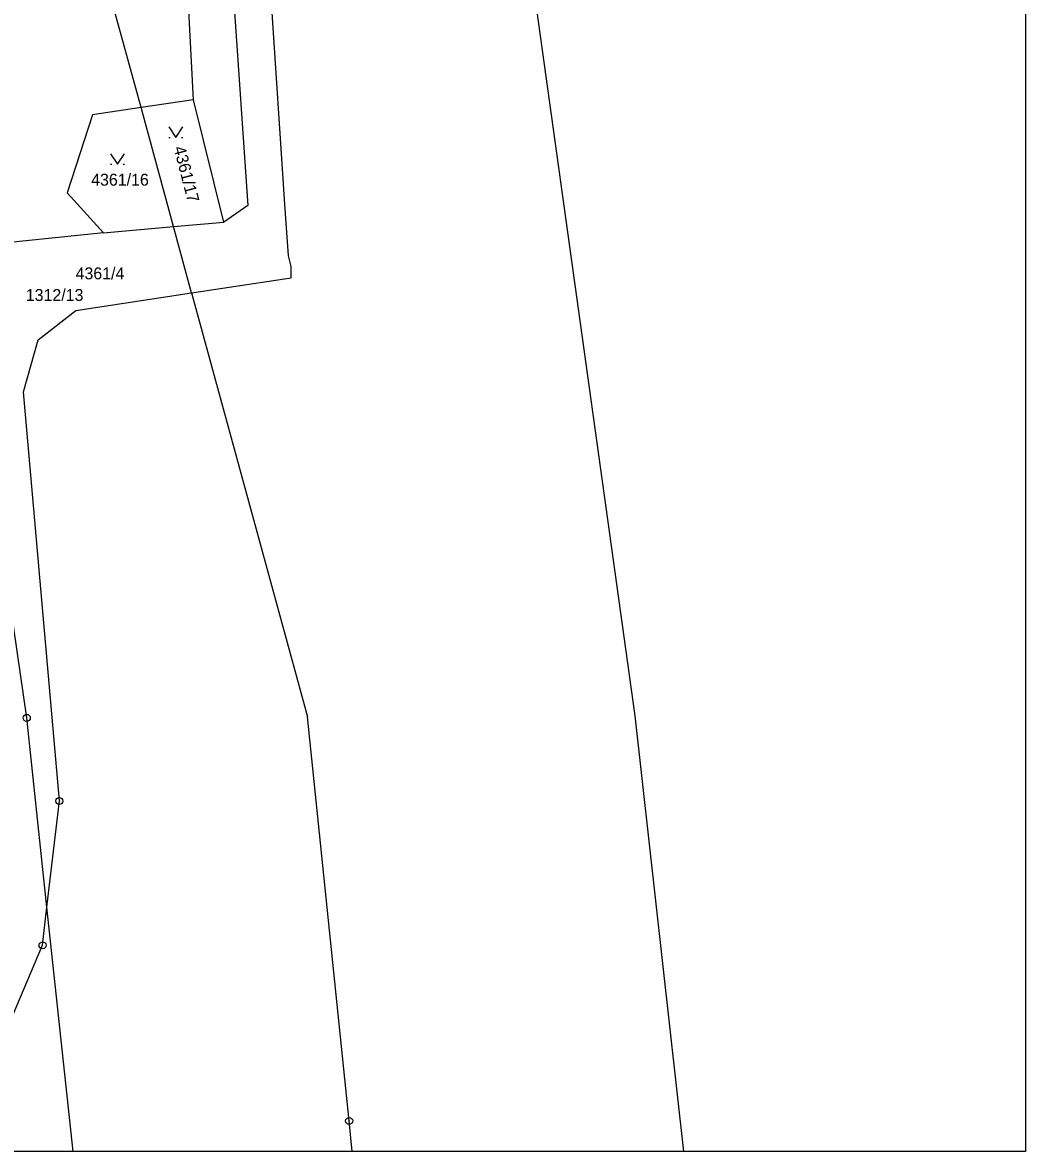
# Model space of a CAD drawing. Extents: x -468021 to -466942, y -1130484 to -1128584.
# Drawn here: x -467084.7 to -466941.7, y -1130484.4 to -1130323.6 of the extents above; entities that cross this region are included whole.
import ezdxf

# ---------------------------------------------------------------- set-up
doc = ezdxf.new("R2010")
doc.units = 0
doc.layers.add('Default', color=7, linetype='Continuous')
doc.layers.add('DKM', color=7, linetype='Continuous')

msp = doc.modelspace()

# ---------------------------------------------------------------- linework, layer by layer
at = {"layer": 'Default'}
msp.add_lwpolyline([(-468020.6, -1128583.91), (-466941.68, -1128583.91), (-466941.68, -1130484.41), (-468020.6, -1130484.41)], close=True, dxfattribs=at)
at = {"layer": 'DKM'}
for p, q in [((-467060.3, -1130334.54), (-467066.16, -1130221.36)), ((-467067.76, -1130335.66), (-467093.02, -1130243.16)), ((-467047.25, -1130349.45), (-467051.18, -1130290.04)), ((-467056.42, -1130292.28), (-467052.56, -1130349.64)), ((-466997.31, -1130422.33), (-467011.79, -1130318.54)), ((-467060.3, -1130334.54), (-467067.76, -1130335.66)), ((-467055.97, -1130351.97), (-467060.3, -1130334.54)), ((-467067.76, -1130335.66), (-467074.66, -1130336.7)), ((-467063.13, -1130352.61), (-467067.76, -1130335.66)), ((-467074.66, -1130336.7), (-467078.28, -1130347.79)), ((-467063.81, -1130338.41), (-467062.81, -1130339.91)), ((-467062.81, -1130339.91), (-467061.81, -1130338.41)), ((-467063.81, -1130339.91), (-467063.61, -1130339.91)), ((-467062.01, -1130339.91), (-467061.81, -1130339.91)), ((-467072.11, -1130342.24), (-467071.11, -1130343.74)), ((-467071.11, -1130343.74), (-467070.11, -1130342.24)), ((-467072.11, -1130343.74), (-467071.91, -1130343.74)), ((-467070.31, -1130343.74), (-467070.11, -1130343.74)), ((-467078.28, -1130347.79), (-467073.12, -1130353.51)), ((-467052.56, -1130349.64), (-467055.97, -1130351.97)), ((-467046.75, -1130356.78), (-467047.25, -1130349.45)), ((-467063.13, -1130352.61), (-467055.97, -1130351.97)), ((-467073.12, -1130353.51), (-467087.38, -1130354.99)), ((-467073.12, -1130353.51), (-467063.13, -1130352.61)), ((-467060.55, -1130362.07), (-467063.13, -1130352.61)), ((-467046.36, -1130358.29), (-467046.75, -1130356.78)), ((-467046.36, -1130359.93), (-467046.36, -1130358.29)), ((-467060.55, -1130362.07), (-467046.36, -1130359.93)), ((-467077.07, -1130364.57), (-467060.55, -1130362.07)), ((-467060.55, -1130362.07), (-467044.05, -1130422.49)), ((-467082.43, -1130368.74), (-467077.07, -1130364.57)), ((-467084.53, -1130376.17), (-467082.43, -1130368.74)), ((-467079.4, -1130434.47), (-467084.53, -1130376.17)), ((-467084.05, -1130422.63), (-467090.42, -1130378.87)), ((-467081.17, -1130449.59), (-467084.05, -1130422.63)), ((-467038.09, -1130480.07), (-467044.05, -1130422.49)), ((-466990.36, -1130484.41), (-466997.31, -1130422.33)), ((-467081.17, -1130449.59), (-467079.4, -1130434.47)), ((-467081.8, -1130455.03), (-467081.17, -1130449.59)), ((-467077.44, -1130484.41), (-467081.17, -1130449.59)), ((-467092.02, -1130479.06), (-467081.8, -1130455.03)), ((-467037.64, -1130484.41), (-467038.09, -1130480.07))]:
    msp.add_line(p, q, dxfattribs=at)
for centre, radius in [((-467084.05, -1130422.63), 0.5), ((-467084.05, -1130422.63), 0.01), ((-467079.4, -1130434.47), 0.5), ((-467079.4, -1130434.47), 0.01), ((-467081.8, -1130455.03), 0.5), ((-467081.8, -1130455.03), 0.01), ((-467038.09, -1130480.07), 0.5), ((-467038.09, -1130480.07), 0.01)]:
    msp.add_circle(centre, radius, dxfattribs=at)

# ---------------------------------------------------------------- texts
msp.add_text('4361/17', height=1.7, rotation=284.6098, dxfattribs=at).set_placement((-467063.13, -1130341.39))
for s, p in [('4361/16', (-467074.87, -1130346.79)), ('4361/4', (-467077.09, -1130360.14)), ('1312/13', (-467084.19, -1130363.22))]:
    msp.add_text(s, height=1.7, dxfattribs=at).set_placement(p)

doc.saveas('drawing.dxf')
